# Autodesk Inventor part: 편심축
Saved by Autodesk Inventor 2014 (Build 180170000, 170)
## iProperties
Created: 2026-03
Part Number: 편심축
Material: 강철, 탄소
Document SubType Name: Modeling
Designer: dg
Density: 7.87 g/cm^3
Appearance: 반연마
Mass: 134.759 g
Surface Area: 51.578 cm^2
Volume: 17.1231 cm^3
Author: jhkim
Creation Date: 2025-06-27
Sending System: Autodesk Inventor 2026
Preprocessor: ST-DEVELOPER v20.1
Author: dg
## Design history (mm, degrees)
node "편심축1"
node "솔리드1"
node "기준1"
